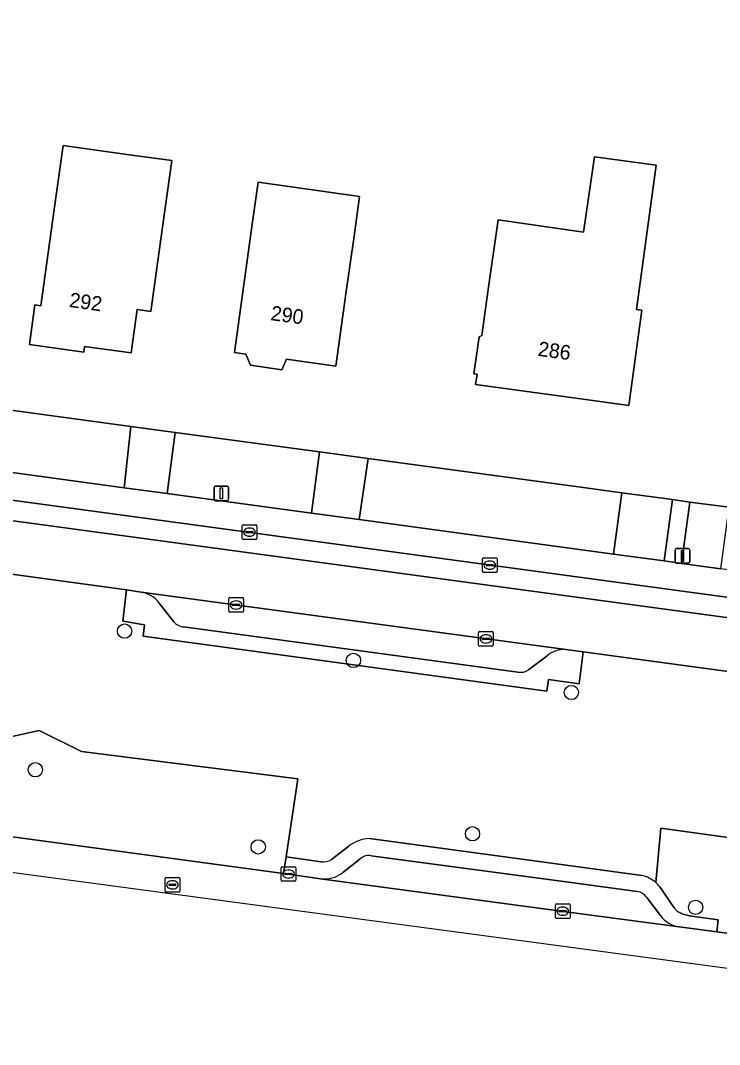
# Model space of a CAD drawing. Extents: x 161692 to 162379, y 380760 to 381678.
# Drawn here: x 161962.2 to 162010, y 380779.1 to 380849.1 of the extents above; entities that cross this region are included whole.
import ezdxf

# ---------------------------------------------------------------- set-up
doc = ezdxf.new("R2010")
doc.units = 0
for name, color, linetype in [('IMGEO_Berm_groen', 7, 'Continuous'), ('IMGEO_Boom', 7, 'Continuous'), ('IMGEO_Erf', 7, 'Continuous'), ('IMGEO_Kolk', 7, 'Continuous'), ('IMGEO_Lichtmast', 7, 'Continuous'), ('IMGEO_Pand', 7, 'Continuous'), ('IMGEO_Pand_nummerreeks', 7, 'Continuous'), ('IMGEO_Parkeervlak_open', 7, 'Continuous'), ('IMGEO_Rijbaan_lokaal_gesloten', 7, 'Continuous'), ('IMGEO_Rioolput', 7, 'Continuous'), ('IMGEO_Voetpad_open', 7, 'Continuous')]:
    doc.layers.add(name, color=color, linetype=linetype)

msp = doc.modelspace()

# ---------------------------------------------------------------- linework, layer by layer
at = {"layer": 'IMGEO_Berm_groen'}
for points in [[(161970.596, 380807.038), (161970.679, 380807.83), (161969.203, 380808.068), (161969.449, 380810.213), (161940.415, 380814.186), (161940.112, 380812.007), (161938.529, 380812.215), (161938.414, 380811.451), (161912.142, 380815.03), (161912.259, 380815.78), (161898.545, 380817.613)], [(162040.423, 380798.373), (162035.618, 380798.98), (162035.924, 380801.201), (162000.665, 380805.971), (162000.388, 380803.799), (161998.295, 380804.077), (161998.17, 380803.296), (161970.596, 380807.038)], [(161942.964, 380798.09), (161943.924, 380796.916), (161946.701, 380796.522), (161944.127, 380801.972), (161960.395, 380799.921), (161963.473, 380800.601), (161966.376, 380799.167), (161981.166, 380797.303), (161980.351, 380791.965), (161982.754, 380791.63)], [(162005.619, 380790.206), (162005.959, 380793.923), (162042.929, 380788.793), (162043.649, 380794.03)], [(162042.793, 380787.806), (162042.929, 380788.793), (162005.959, 380793.923), (162005.619, 380790.206)], [(161983.454, 380791.774), (161984.634, 380792.695)], [(161986.05, 380793.223), (162000, 380791.331), (162004.657, 380790.7)], [(162005.906, 380789.91), (162006.873, 380788.479), (162007.116, 380788.236), (162007.416, 380788.074), (162007.654, 380787.992), (162007.916, 380787.941), (162009.877, 380787.648), (162009.782, 380786.834), (162018.39, 380785.673), (162034.725, 380783.435), (162034.844, 380784.31), (162035.785, 380784.182), (162037.925, 380783.892), (162038.1, 380785.181), (162039.071, 380785.049), (162039.764, 380784.955)]]:
    msp.add_lwpolyline(points, dxfattribs=at)
msp.add_lwpolyline([(161981.166, 380797.303), (161966.376, 380799.167), (161963.473, 380800.601), (161960.395, 380799.921), (161944.127, 380801.972), (161946.701, 380796.522), (161946.543, 380795.38), (161955.234, 380794.192), (161980.175, 380790.815), (161980.351, 380791.965)], close=True, dxfattribs=at)
for centre, radius, start, end in [((161986.171, 380790.735), 2.491, 92.78787, 128.11123), ((161982.917, 380792.613), 0.996, 260.60601, 302.64278), ((162004.122, 380788.474), 2.289, 49.15709, 76.48069), ((162004.167, 380788.511), 2.232, 38.81663, 49.41451)]:
    msp.add_arc(centre, radius, start, end, dxfattribs=at)
at = {"layer": 'IMGEO_Boom'}
for centre in [(161969.319, 380807.392), (161984.957, 380805.39), (161999.854, 380803.197), (161963.219, 380797.918), (161993.096, 380793.539), (161978.451, 380792.645), (162008.342, 380788.51)]:
    msp.add_circle(centre, 0.489, dxfattribs=at)
at = {"layer": 'IMGEO_Erf'}
msp.add_lwpolyline([(161902.994, 380830.393), (161906.216, 380829.958), (161917.567, 380828.426), (161920.64, 380828.012), (161941.489, 380825.198), (161944.559, 380824.783), (161956.36, 380823.191), (161959.367, 380822.785), (161969.747, 380821.384), (161972.782, 380820.974), (161982.64, 380819.644), (161985.956, 380819.196), (162000, 380817.301), (162003.3, 380816.856), (162006.759, 380816.389), (162007.953, 380816.216), (162010.645, 380815.865), (162022.543, 380814.259), (162025.665, 380837.887), (162027.29, 380850.188), (162027.58, 380852.385)], dxfattribs=at)
for points in [[(161972.558, 380839.55), (161971.806, 380834.194), (161971.111, 380829.242), (161970.176, 380829.373), (161969.76, 380826.411), (161966.59, 380826.857), (161966.534, 380826.458), (161962.813, 380826.98), (161963.194, 380829.69), (161963.593, 380829.634), (161964.516, 380836.203), (161965.132, 380840.593), (161969.325, 380840.004)], [(162000.684, 380834.664), (162001.423, 380839.8), (162005.639, 380839.233), (162004.314, 380829.385), (162004.663, 380829.338), (162003.783, 380822.804), (162000, 380823.327), (161993.306, 380824.253), (161993.405, 380824.957), (161993.193, 380824.987), (161993.549, 380827.518), (161993.732, 380827.592), (161994.172, 380830.733), (161994.84, 380835.505)], [(161985.38, 380837.107), (161984.999, 380834.395), (161984.446, 380830.454), (161983.75, 380825.502), (161980.383, 380825.975), (161980.069, 380825.26), (161977.918, 380825.562), (161977.607, 380826.333), (161976.823, 380826.443), (161977.519, 380831.395), (161978.062, 380835.362), (161978.444, 380838.082)]]:
    msp.add_lwpolyline(points, close=True, dxfattribs=at)
at = {"layer": 'IMGEO_Kolk'}
for p, q in [((161977.351, 380813.735), (161977.351, 380814.587)), ((161977.426, 380814.661), (161978.278, 380814.661)), ((161977.839, 380814.441), (161977.864, 380814.441)), ((161978.352, 380814.587), (161978.352, 380813.735)), ((161978.278, 380813.661), (161977.426, 380813.661)), ((161977.61, 380814.155), (161977.61, 380814.167)), ((161978.048, 380814.118), (161977.65, 380814.118)), ((161977.653, 380814.204), (161978.051, 380814.204)), ((161977.862, 380813.881), (161977.837, 380813.881)), ((161978.094, 380814.167), (161978.094, 380814.155)), ((161993.772, 380811.48), (161993.772, 380812.332)), ((161993.847, 380812.406), (161994.699, 380812.406)), ((161994.773, 380812.332), (161994.773, 380811.48)), ((161994.031, 380811.9), (161994.031, 380811.912)), ((161994.469, 380811.863), (161994.071, 380811.863)), ((161994.074, 380811.949), (161994.472, 380811.949)), ((161994.283, 380811.626), (161994.258, 380811.626)), ((161994.26, 380812.186), (161994.285, 380812.186)), ((161994.515, 380811.912), (161994.515, 380811.9)), ((161994.699, 380811.406), (161993.847, 380811.406)), ((161976.435, 380808.755), (161976.435, 380809.607)), ((161976.51, 380809.681), (161977.362, 380809.681)), ((161976.923, 380809.461), (161976.948, 380809.461)), ((161977.436, 380809.607), (161977.436, 380808.755)), ((161976.694, 380809.175), (161976.694, 380809.187)), ((161977.132, 380809.138), (161976.734, 380809.138)), ((161976.737, 380809.224), (161977.135, 380809.224)), ((161976.946, 380808.901), (161976.921, 380808.901)), ((161977.178, 380809.187), (161977.178, 380809.175)), ((161977.362, 380808.681), (161976.51, 380808.681)), ((161993.59, 380807.359), (161994.442, 380807.359)), ((161993.515, 380806.433), (161993.515, 380807.285)), ((161993.774, 380806.853), (161993.774, 380806.865)), ((161994.212, 380806.816), (161993.814, 380806.816)), ((161993.817, 380806.902), (161994.215, 380806.902)), ((161994.003, 380807.139), (161994.028, 380807.139)), ((161994.258, 380806.865), (161994.258, 380806.853)), ((161994.516, 380807.285), (161994.516, 380806.433)), ((161994.442, 380806.359), (161993.59, 380806.359)), ((161994.026, 380806.579), (161994.001, 380806.579)), ((161980.095, 380791.292), (161980.947, 380791.292)), ((161980.02, 380790.366), (161980.02, 380791.218)), ((161980.279, 380790.786), (161980.279, 380790.798)), ((161980.717, 380790.749), (161980.319, 380790.749)), ((161980.322, 380790.835), (161980.72, 380790.835)), ((161980.508, 380791.072), (161980.533, 380791.072)), ((161980.763, 380790.798), (161980.763, 380790.786)), ((161981.021, 380791.218), (161981.021, 380790.366)), ((161980.947, 380790.292), (161980.095, 380790.292)), ((161980.531, 380790.512), (161980.506, 380790.512)), ((161998.761, 380787.822), (161998.761, 380788.674)), ((161998.836, 380788.748), (161999.688, 380788.748)), ((161999.249, 380788.528), (161999.274, 380788.528)), ((161999.762, 380788.674), (161999.762, 380787.822)), ((161999.688, 380787.748), (161998.836, 380787.748)), ((161999.02, 380788.242), (161999.02, 380788.254)), ((161999.458, 380788.205), (161999.06, 380788.205)), ((161999.063, 380788.291), (161999.461, 380788.291)), ((161999.272, 380787.968), (161999.247, 380787.968)), ((161999.504, 380788.254), (161999.504, 380788.242))]:
    msp.add_line(p, q, dxfattribs=at)
for points in [[(161977.351, 380813.735), (161977.351, 380814.587)], [(161977.426, 380814.661), (161978.278, 380814.661)], [(161978.352, 380814.587), (161978.352, 380813.735)], [(161978.278, 380813.661), (161977.426, 380813.661)], [(161993.772, 380811.48), (161993.772, 380812.332)], [(161993.847, 380812.406), (161994.699, 380812.406)], [(161994.773, 380812.332), (161994.773, 380811.48)], [(161994.699, 380811.406), (161993.847, 380811.406)], [(161976.435, 380808.755), (161976.435, 380809.607)], [(161976.51, 380809.681), (161977.362, 380809.681)], [(161977.436, 380809.607), (161977.436, 380808.755)], [(161977.362, 380808.681), (161976.51, 380808.681)], [(161993.59, 380807.359), (161994.442, 380807.359)], [(161993.515, 380806.433), (161993.515, 380807.285)], [(161994.516, 380807.285), (161994.516, 380806.433)], [(161994.442, 380806.359), (161993.59, 380806.359)], [(161980.095, 380791.292), (161980.947, 380791.292)], [(161980.02, 380790.366), (161980.02, 380791.218)], [(161981.021, 380791.218), (161981.021, 380790.366)], [(161980.947, 380790.292), (161980.095, 380790.292)], [(161998.761, 380787.822), (161998.761, 380788.674)], [(161998.836, 380788.748), (161999.688, 380788.748)], [(161999.762, 380788.674), (161999.762, 380787.822)], [(161999.688, 380787.748), (161998.836, 380787.748)]]:
    msp.add_lwpolyline(points, dxfattribs=at)
for centre, radius, start, end in [((161977.428, 380814.585), 0.0765, 91.55205, 178.44795), ((161977.428, 380814.585), 0.0765, 91.55205, 178.44795), ((161978.276, 380814.585), 0.0765, 1.55205, 88.44795), ((161978.276, 380814.585), 0.0765, 1.55205, 88.44795), ((161977.428, 380813.737), 0.0765, 181.55205, 268.44795), ((161977.428, 380813.737), 0.0765, 181.55205, 268.44795), ((161977.65, 380814.164), 0.0403, 85.87752, 175.75265), ((161977.647, 380814.154), 0.0366, 178.93798, 274.71019), ((161978.051, 380814.161), 0.043, 264.86636, 352.45326), ((161978.055, 380814.166), 0.0386, 1.73085, 96.63898), ((161978.276, 380813.737), 0.0765, 271.55205, 358.44795), ((161978.276, 380813.737), 0.0765, 271.55205, 358.44795), ((161993.849, 380812.33), 0.0765, 91.55205, 178.44795), ((161993.849, 380812.33), 0.0765, 91.55205, 178.44795), ((161994.697, 380812.33), 0.0765, 1.55205, 88.44795), ((161994.697, 380812.33), 0.0765, 1.55205, 88.44795), ((161994.071, 380811.909), 0.0403, 85.87752, 175.75265), ((161994.068, 380811.899), 0.0366, 178.93798, 274.71019), ((161994.472, 380811.906), 0.043, 264.86636, 352.45326), ((161994.476, 380811.911), 0.0386, 1.73085, 96.63898), ((161993.849, 380811.482), 0.0765, 181.55205, 268.44795), ((161993.849, 380811.482), 0.0765, 181.55205, 268.44795), ((161994.697, 380811.482), 0.0765, 271.55205, 358.44795), ((161994.697, 380811.482), 0.0765, 271.55205, 358.44795), ((161976.512, 380809.605), 0.0765, 91.55205, 178.44795), ((161976.512, 380809.605), 0.0765, 91.55205, 178.44795), ((161977.36, 380809.605), 0.0765, 1.55205, 88.44795), ((161977.36, 380809.605), 0.0765, 1.55205, 88.44795), ((161976.512, 380808.757), 0.0765, 181.55205, 268.44795), ((161976.512, 380808.757), 0.0765, 181.55205, 268.44795), ((161976.734, 380809.184), 0.0403, 85.87752, 175.75265), ((161976.731, 380809.174), 0.0366, 178.93798, 274.71019), ((161977.135, 380809.181), 0.043, 264.86636, 352.45326), ((161977.139, 380809.186), 0.0386, 1.73085, 96.63898), ((161977.36, 380808.757), 0.0765, 271.55205, 358.44795), ((161977.36, 380808.757), 0.0765, 271.55205, 358.44795), ((161993.592, 380807.283), 0.0765, 91.55205, 178.44795), ((161993.592, 380807.283), 0.0765, 91.55205, 178.44795), ((161994.44, 380807.283), 0.0765, 1.55205, 88.44795), ((161994.44, 380807.283), 0.0765, 1.55205, 88.44795), ((161993.814, 380806.862), 0.0403, 85.87752, 175.75265), ((161993.811, 380806.852), 0.0366, 178.93798, 274.71019), ((161994.215, 380806.859), 0.043, 264.86636, 352.45326), ((161994.219, 380806.864), 0.0386, 1.73085, 96.63898), ((161993.592, 380806.435), 0.0765, 181.55205, 268.44795), ((161993.592, 380806.435), 0.0765, 181.55205, 268.44795), ((161994.44, 380806.435), 0.0765, 271.55205, 358.44795), ((161994.44, 380806.435), 0.0765, 271.55205, 358.44795), ((161980.097, 380791.216), 0.0765, 91.55205, 178.44795), ((161980.097, 380791.216), 0.0765, 91.55205, 178.44795), ((161980.945, 380791.216), 0.0765, 1.55205, 88.44795), ((161980.945, 380791.216), 0.0765, 1.55205, 88.44795), ((161980.319, 380790.795), 0.0403, 85.87752, 175.75265), ((161980.316, 380790.785), 0.0366, 178.93798, 274.71019), ((161980.72, 380790.792), 0.043, 264.86636, 352.45326), ((161980.724, 380790.797), 0.0386, 1.73085, 96.63898), ((161980.097, 380790.368), 0.0765, 181.55205, 268.44795), ((161980.097, 380790.368), 0.0765, 181.55205, 268.44795), ((161980.945, 380790.368), 0.0765, 271.55205, 358.44795), ((161980.945, 380790.368), 0.0765, 271.55205, 358.44795), ((161998.838, 380788.672), 0.0765, 91.55205, 178.44795), ((161998.838, 380788.672), 0.0765, 91.55205, 178.44795), ((161999.686, 380788.672), 0.0765, 1.55205, 88.44795), ((161999.686, 380788.672), 0.0765, 1.55205, 88.44795), ((161998.838, 380787.824), 0.0765, 181.55205, 268.44795), ((161998.838, 380787.824), 0.0765, 181.55205, 268.44795), ((161999.06, 380788.251), 0.0403, 85.87752, 175.75265), ((161999.057, 380788.241), 0.0366, 178.93798, 274.71019), ((161999.461, 380788.248), 0.043, 264.86636, 352.45326), ((161999.465, 380788.253), 0.0386, 1.73085, 96.63898), ((161999.686, 380787.824), 0.0765, 271.55205, 358.44795), ((161999.686, 380787.824), 0.0765, 271.55205, 358.44795)]:
    msp.add_arc(centre, radius, start, end, dxfattribs=at)
for centre, major_axis, ratio, start_param, end_param in [((161977.838, 380814.161), (-0.387, 0.002), 0.722429, 4.712389, 7.853982), ((161977.863, 380814.161), (-0.39, 0.002), 0.717154, 1.570796, 4.712389), ((161994.259, 380811.906), (-0.387, 0.002), 0.722429, 4.712389, 7.853982), ((161994.284, 380811.906), (-0.39, 0.002), 0.717154, 1.570796, 4.712389), ((161976.922, 380809.181), (-0.387, 0.002), 0.722429, 4.712389, 7.853982), ((161976.947, 380809.181), (-0.39, 0.002), 0.717154, 1.570796, 4.712389), ((161994.002, 380806.859), (-0.387, 0.002), 0.722429, 4.712389, 7.853982), ((161994.027, 380806.859), (-0.39, 0.002), 0.717154, 1.570796, 4.712389), ((161980.507, 380790.792), (-0.387, 0.002), 0.722429, 4.712389, 7.853982), ((161980.532, 380790.792), (-0.39, 0.002), 0.717154, 1.570796, 4.712389), ((161999.248, 380788.248), (-0.387, 0.002), 0.722429, 4.712389, 7.853982), ((161999.273, 380788.248), (-0.39, 0.002), 0.717154, 1.570796, 4.712389)]:
    msp.add_ellipse(centre, major_axis=major_axis, ratio=ratio, start_param=start_param, end_param=end_param, dxfattribs=at)
at = {"layer": 'IMGEO_Lichtmast'}
for p, q in [((161975.442, 380816.401), (161975.442, 380817.201)), ((161975.442, 380817.201), (161975.442, 380816.401)), ((161975.542, 380817.301), (161976.332, 380817.301)), ((161976.332, 380817.301), (161975.542, 380817.301)), ((161976.432, 380817.201), (161976.432, 380816.401)), ((161976.432, 380816.401), (161976.432, 380817.201)), ((161976.332, 380816.301), (161975.542, 380816.301)), ((161975.542, 380816.301), (161976.332, 380816.301)), ((162006.947, 380812.137), (162006.947, 380812.937)), ((162006.947, 380812.937), (162006.947, 380812.137)), ((162007.047, 380813.037), (162007.837, 380813.037)), ((162007.837, 380813.037), (162007.047, 380813.037)), ((162007.937, 380812.937), (162007.937, 380812.137)), ((162007.937, 380812.137), (162007.937, 380812.937)), ((162007.837, 380812.037), (162007.047, 380812.037)), ((162007.047, 380812.037), (162007.837, 380812.037))]:
    msp.add_line(p, q, dxfattribs=at)
for points in [[(161975.862, 380817.176), (161976.012, 380817.176), (161976.012, 380816.426), (161975.862, 380816.426), (161975.862, 380817.176)], [(162007.367, 380812.912), (162007.517, 380812.912), (162007.517, 380812.162), (162007.367, 380812.162), (162007.367, 380812.912)]]:
    msp.add_lwpolyline(points, dxfattribs=at)
for centre, start, end in [((161975.542, 380817.201), 90, 180), ((161975.542, 380817.201), 90, 180), ((161976.332, 380817.201), 0, 90), ((161976.332, 380817.201), 360, 90), ((161975.542, 380816.401), 180, 270), ((161975.542, 380816.401), 180, 270), ((161976.332, 380816.401), 270, 0), ((161976.332, 380816.401), 270, 0), ((162007.047, 380812.937), 90, 180), ((162007.047, 380812.937), 90, 180), ((162007.837, 380812.937), 0, 90), ((162007.837, 380812.937), 360, 90), ((162007.047, 380812.137), 180, 270), ((162007.047, 380812.137), 180, 270), ((162007.837, 380812.137), 270, 0), ((162007.837, 380812.137), 270, 0)]:
    msp.add_arc(centre, 0.1, start, end, dxfattribs=at)
at = {"layer": 'IMGEO_Pand'}
for points in [[(161971.806, 380834.194), (161972.558, 380839.55), (161969.325, 380840.004), (161965.132, 380840.593), (161964.516, 380836.203), (161963.593, 380829.634), (161963.194, 380829.69), (161962.813, 380826.98), (161966.534, 380826.458), (161966.59, 380826.857), (161969.76, 380826.411), (161970.176, 380829.373), (161971.111, 380829.242)], [(162001.423, 380839.8), (162000.684, 380834.664), (161994.84, 380835.505), (161994.172, 380830.733), (161993.732, 380827.592), (161993.549, 380827.518), (161993.193, 380824.987), (161993.405, 380824.957), (161993.306, 380824.253), (162000, 380823.327), (162003.783, 380822.804), (162004.663, 380829.338), (162004.314, 380829.385), (162005.639, 380839.233)], [(161984.446, 380830.454), (161984.999, 380834.395), (161985.38, 380837.107), (161978.444, 380838.082), (161978.062, 380835.362), (161977.519, 380831.395), (161976.823, 380826.443), (161977.607, 380826.333), (161977.918, 380825.562), (161980.069, 380825.26), (161980.383, 380825.975), (161983.75, 380825.502)]]:
    msp.add_lwpolyline(points, close=True, dxfattribs=at)
at = {"layer": 'IMGEO_Parkeervlak_open'}
for points in [[(162016.852, 380810.742), (162010.075, 380811.66), (162007.385, 380812.025), (162006.192, 380812.187), (162002.733, 380812.656), (161985.346, 380815.014), (161982.089, 380815.455), (161972.239, 380816.792), (161969.295, 380817.193), (161958.799, 380818.621), (161955.808, 380819.028), (161944.021, 380820.632), (161940.941, 380821.051), (161924.029, 380823.352)], [(161920.649, 380821.91), (162019.525, 380808.483)], [(161999.463, 380806.128), (161970.442, 380810.065)], [(161971.676, 380809.315), (161972.68, 380808.038)], [(161973.355, 380807.679), (161996.19, 380804.597)], [(161996.928, 380804.748), (161998.199, 380805.701)], [(162004.353, 380789.598), (162000, 380790.182), (161986.168, 380792.038)], [(161985.428, 380791.835), (161984.205, 380790.861)], [(161982.699, 380790.464), (162000, 380788.148), (162007.226, 380787.18)], [(162005.942, 380787.96), (162005.01, 380789.187)]]:
    msp.add_lwpolyline(points, dxfattribs=at)
for centre, radius, start, end in [((161970.147, 380808.19), 1.898, 36.3517, 81.06754), ((161973.436, 380808.646), 0.97, 218.78418, 265.2031), ((161999.334, 380804.427), 1.706, 85.64887, 131.68276), ((161996.38, 380805.55), 0.971, 258.74895, 304.37808), ((161985.991, 380791.234), 0.823, 77.56694, 133.11357), ((161982.942, 380792.596), 2.146, 263.49356, 306.04225), ((162004.141, 380788.529), 1.09, 37.15323, 78.78898), ((162007.498, 380789.075), 1.915, 215.62457, 261.82002)]:
    msp.add_arc(centre, radius, start, end, dxfattribs=at)
at = {"layer": 'IMGEO_Rijbaan_lokaal_gesloten'}
for points in [[(161814.137, 380834.931), (162153.114, 380788.982), (162173.589, 380787.538), (162178.941, 380786.895), (162192.055, 380785.129), (162226.418, 380780.403), (162229.289, 380780.178), (162234.771, 380780.432)], [(162234.785, 380779.843), (162234.771, 380780.432), (162229.289, 380780.178), (162226.418, 380780.403), (162192.055, 380785.129), (162178.941, 380786.895), (162173.589, 380787.538), (162153.114, 380788.982), (161814.137, 380834.931)], [(161807.026, 380819.109), (161803.167, 380819.836), (161798.009, 380820.862), (161779.286, 380823.639), (161756.857, 380826.07), (161745.638, 380827.554), (161735.173, 380829.227), (161731.252, 380829.951), (161723.185, 380831.715), (161719.797, 380832.442), (161719.379, 380829.094), (161765.369, 380823.138), (161807.579, 380816.265), (161826.791, 380811.355), (161859.959, 380804.218), (161914.65, 380797.204), (162022.247, 380782.773), (162063.3, 380779.137)], [(161785.735, 380831.837), (161803.94, 380831.083), (161806.77, 380830.885), (161820.431, 380830.418), (161834.49, 380828.566), (161845.222, 380827.099), (161887.661, 380821.279), (161891.404, 380820.778), (161898.822, 380819.796), (161910.997, 380818.145), (161940.127, 380814.227), (161940.415, 380814.186), (161969.449, 380810.213), (161970.442, 380810.065), (161999.463, 380806.128), (162000.665, 380805.971), (162035.924, 380801.201), (162040.702, 380800.555), (162059.025, 380798.069)], [(162019.525, 380808.483), (161920.649, 380821.91)], [(162055.847, 380780.609), (162039.323, 380782.845), (162037.699, 380783.049), (162035.667, 380783.312), (162034.725, 380783.435), (162018.39, 380785.673), (162009.782, 380786.834), (162007.226, 380787.18), (162000, 380788.148), (161982.699, 380790.464), (161980.517, 380790.791), (161980.175, 380790.815), (161955.234, 380794.192), (161946.543, 380795.38), (161943.996, 380795.73), (161918.776, 380799.132), (161916.171, 380799.476), (161914.571, 380799.711), (161912.13, 380800.044), (161902.44, 380801.366)]]:
    msp.add_lwpolyline(points, dxfattribs=at)
at = {"layer": 'IMGEO_Rioolput'}
for p, q in [((161972.162, 380790.554), (161973.014, 380790.554)), ((161972.087, 380789.628), (161972.087, 380790.48)), ((161972.346, 380790.048), (161972.346, 380790.06)), ((161972.784, 380790.011), (161972.386, 380790.011)), ((161972.389, 380790.097), (161972.787, 380790.097)), ((161972.575, 380790.334), (161972.6, 380790.334)), ((161972.83, 380790.06), (161972.83, 380790.048)), ((161973.088, 380790.48), (161973.088, 380789.628)), ((161973.014, 380789.554), (161972.162, 380789.554)), ((161972.598, 380789.774), (161972.573, 380789.774))]:
    msp.add_line(p, q, dxfattribs=at)
for points in [[(161972.162, 380790.554), (161973.014, 380790.554)], [(161972.087, 380789.628), (161972.087, 380790.48)], [(161973.088, 380790.48), (161973.088, 380789.628)], [(161973.014, 380789.554), (161972.162, 380789.554)]]:
    msp.add_lwpolyline(points, dxfattribs=at)
for centre, radius, start, end in [((161972.164, 380790.478), 0.0765, 91.55205, 178.44795), ((161972.164, 380790.478), 0.0765, 91.55205, 178.44795), ((161973.012, 380790.478), 0.0765, 1.55205, 88.44795), ((161973.012, 380790.478), 0.0765, 1.55205, 88.44795), ((161972.386, 380790.057), 0.0403, 85.87752, 175.75265), ((161972.383, 380790.047), 0.0366, 178.93798, 274.71019), ((161972.787, 380790.054), 0.043, 264.86636, 352.45326), ((161972.791, 380790.059), 0.0386, 1.73085, 96.63898), ((161972.164, 380789.63), 0.0765, 181.55205, 268.44795), ((161972.164, 380789.63), 0.0765, 181.55205, 268.44795), ((161973.012, 380789.63), 0.0765, 271.55205, 358.44795), ((161973.012, 380789.63), 0.0765, 271.55205, 358.44795)]:
    msp.add_arc(centre, radius, start, end, dxfattribs=at)
for centre, major_axis, ratio, start_param, end_param in [((161972.574, 380790.054), (-0.387, 0.002), 0.722429, 4.712389, 7.853982), ((161972.599, 380790.054), (-0.39, 0.002), 0.717154, 1.570796, 4.712389)]:
    msp.add_ellipse(centre, major_axis=major_axis, ratio=ratio, start_param=start_param, end_param=end_param, dxfattribs=at)
at = {"layer": 'IMGEO_Voetpad_open'}
for points in [[(161959.367, 380822.785), (161958.799, 380818.621), (161969.295, 380817.193), (161969.747, 380821.384)], [(161969.747, 380821.384), (161969.295, 380817.193), (161972.239, 380816.792), (161972.782, 380820.974)], [(161972.782, 380820.974), (161972.239, 380816.792), (161982.089, 380815.455), (161982.64, 380819.644)], [(161982.64, 380819.644), (161982.089, 380815.455), (161985.346, 380815.014), (161985.956, 380819.196)], [(162002.733, 380812.656), (162003.3, 380816.856), (162000, 380817.301), (161985.956, 380819.196), (161985.346, 380815.014)], [(162003.3, 380816.856), (162002.733, 380812.656), (162006.192, 380812.187), (162006.759, 380816.389)], [(162007.385, 380812.025), (162007.953, 380816.216), (162006.759, 380816.389), (162006.192, 380812.187)], [(162010.075, 380811.66), (162010.645, 380815.865), (162007.953, 380816.216), (162007.385, 380812.025)]]:
    msp.add_lwpolyline(points, close=True, dxfattribs=at)
for points in [[(161970.442, 380810.065), (161969.449, 380810.213), (161969.203, 380808.068), (161970.679, 380807.83), (161970.596, 380807.038), (161998.17, 380803.296), (161998.295, 380804.077), (162000.388, 380803.799), (162000.665, 380805.971), (161999.463, 380806.128)], [(161972.68, 380808.038), (161971.676, 380809.315)], [(161996.19, 380804.597), (161973.355, 380807.679)], [(161998.199, 380805.701), (161996.928, 380804.748)], [(161984.634, 380792.695), (161983.454, 380791.774)], [(162004.657, 380790.7), (162000, 380791.331), (161986.05, 380793.223)], [(161982.754, 380791.63), (161980.351, 380791.965), (161980.175, 380790.815), (161980.517, 380790.791), (161982.699, 380790.464)], [(161986.168, 380792.038), (162000, 380790.182), (162004.353, 380789.598)], [(161984.205, 380790.861), (161985.428, 380791.835)], [(162007.226, 380787.18), (162009.782, 380786.834), (162009.877, 380787.648), (162007.916, 380787.941), (162007.654, 380787.992), (162007.416, 380788.074), (162007.116, 380788.236), (162006.873, 380788.479), (162005.906, 380789.91)], [(162005.01, 380789.187), (162005.942, 380787.96)]]:
    msp.add_lwpolyline(points, dxfattribs=at)
for centre, radius, start, end in [((161970.147, 380808.19), 1.898, 36.3517, 81.06754), ((161973.436, 380808.646), 0.97, 218.78418, 265.2031), ((161999.334, 380804.427), 1.706, 85.64887, 131.68276), ((161996.38, 380805.55), 0.971, 258.74895, 304.37808), ((161986.171, 380790.735), 2.491, 92.78787, 128.11123), ((161985.991, 380791.234), 0.823, 77.56694, 133.11357), ((161982.917, 380792.613), 0.996, 260.60601, 302.64278), ((161982.942, 380792.596), 2.146, 263.49356, 306.04225), ((162004.122, 380788.474), 2.289, 49.15709, 76.48069), ((162004.167, 380788.511), 2.232, 38.81663, 49.41451), ((162004.141, 380788.529), 1.09, 37.15323, 78.78898), ((162007.498, 380789.075), 1.915, 215.62457, 261.82002)]:
    msp.add_arc(centre, radius, start, end, dxfattribs=at)

# ---------------------------------------------------------------- texts
at = {"layer": 'IMGEO_Pand_nummerreeks'}
for s, rotation, p in [('292', 351.99139, (161965.497, 380829.555)), ('290', 352.26399, (161979.263, 380828.654)), ('286', 352.12578, (161997.525, 380826.214))]:
    msp.add_text(s, height=1, rotation=rotation, dxfattribs=at).set_placement(p)

doc.saveas('drawing.dxf')
